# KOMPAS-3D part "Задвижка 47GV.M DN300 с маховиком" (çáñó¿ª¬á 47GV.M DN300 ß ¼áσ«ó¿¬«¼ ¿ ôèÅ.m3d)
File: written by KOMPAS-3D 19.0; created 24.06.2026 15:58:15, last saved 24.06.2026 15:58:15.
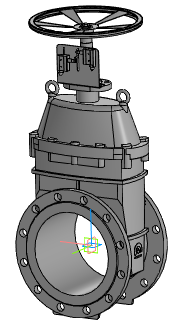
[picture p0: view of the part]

Document properties: Автор: Энергия; Полное имя файла: Z:\3.Личные\sachek\Dendor\3D для проектировщиков\2.7 Тип 47GV.M Задвижка клиновая фланцевая с обрезиненным клином\47GV.M DN300\Задвижка 47GV.M DN300 с маховиком.a3d

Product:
- Part/product: Задвижка 47GV.M DN300 с маховиком
    Масса: 231.457
    source file: ..\47GV.M DN300\DR.47GVM.300.16.00.000 - Задвижка с обрезиненным клином DN300.spw
  - Component: Задвижка с обрезиненным клином DN300. Сборочный чертеж  | designation DR.47GVM.300.16.00.000СБ  | pos. 0  | Масса: 108.933; Раздел спецификации: Документация; Форматы листов документа: 2xA3; source file: ..\..\..\47GVM\DR.47GVM.300.16.00.000\DR.47GVM.300.16.00.000 СБ - Задвижка с обрезиненным клином DN300.cdw

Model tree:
1. Операция без истории:1

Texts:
  Точка начала. Х
  Точка начала. Y
  Точка начала. Z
